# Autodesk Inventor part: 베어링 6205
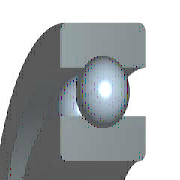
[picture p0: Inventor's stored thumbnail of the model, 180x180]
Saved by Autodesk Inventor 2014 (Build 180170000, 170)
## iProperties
Created: 2012-02
Part Number: 베어링 6205
Material: 강철, 연강
Description: 깊은 그루브 볼 베어링
Document SubType Name: Modeling
Standard: KS B 2023
Designer: mduedu
Standards Organization: KS
Language: ko-KR
Size Designation: 6205 - 25 x 52 x 15
Categories: <MemberInstance><Categories><Category DisplayName="샤프트 부품" InternalName="7f7aeb1f-a693-4053-b835-cee3144e0d98" Mnemonic="SHFT"><Category DisplayName="베어링" Inter
Density: 1 g/cm^3
Appearance: Yellow
IsCustomPart: 1
Author: mduedu
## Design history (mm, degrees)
sketch "스케치" dims "d0" = 7.02 (= -0.26 x WD + 0.26 x BD)
  geometry: L1 (3.99, 19.25)-(11.01, 19.25); L2 (7.5, 19.25)-(7.5, 15.74); L3 (7.5, 19.25)-(7.5, 22.76); L4 (4.892, 16.901)-(0, 16.901); L5 (0, 12.5)-(15, 12.5); L6 (4.892, 21.599)-(0, 21.599); L7 (0, 26)-(15, 26); L8 (15, 12.5)-(15, 16.901); L9 (10.108, 16.901)-(15, 16.901); L10 (10.108, 21.599)-(15, 21.599); L11 (15, 26)-(15, 21.599); L12 (-1.4, 0)-(8.4, 0) reference; L13 (0, -0.3)-(0, 5.3) reference
  constraints: 22 end point, 4 point on line, 2 collinear, 2 perpendicular, 2 symmetric about line, 1 midpoint, 1 parallel, 14 other
  dimensions: "d9" = 25 diameter of L5 L12 (= WD); "d11" = 52 diameter of L7 L12 (= BD); "d12" = 15 distance between parallel lines of L8 L13 (= KB); "d13" = 33.802 diameter of L9 L12 (= 0.326 x BD + 0.674 x WD)
revolve "본체" stored, may be unused: angle "d6" = 90 deg
revolve "볼" stored, may be unused: angle "d7" = 90 deg
pattern_circular "IDS_ARRAYBALL[SIMPL:T]" dims angle "d3" = 360 deg
body "Solid1"
fillet "모깎기1" dims "d1" = 1 (= KRS)
other parameters: "WD" = 25 [user parameter; used in 5 equation terms], "BD" = 52 [user parameter; used in 5 equation terms], "KB" = 15 [user parameter; used in 1 equation term], "KRS" = 1 [user parameter; used in 1 equation term], "d4" = 0, "d5" = 0, "d8" = 0, "d14" = 0, "d15" = 0, "BBA" = 0 [user parameter], "BC0" = 7800000 [user parameter], "BC" = 1.4e+07 [user parameter], "BR" = 26 (= 0.5 x BD) [user parameter], "WR" = 12.5 (= 0.5 x WD) [user parameter]
